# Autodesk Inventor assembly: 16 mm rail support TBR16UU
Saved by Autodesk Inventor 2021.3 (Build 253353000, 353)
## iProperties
Created: 2022-03
Part Number: 16 mm rail support TBR16UU
Document SubType Name: Assembly
Designer: Administrator
Title: 16 mm rail support TBR16UU v1
Author: Administrator
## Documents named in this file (3)
- c:\worker\convert-fusion-r02\tmp\job-1\4458\output\files\16542e95-d20b-4160-a815-438acdfd5590\2a808a41-fb52-4cbf-ad3c-1d9b1d9263a2.iam
- c:\worker\convert-fusion-r02\tmp\job-1\4458\output\files\16542e95-d20b-4160-a815-438acdfd5590\TBR16UU.ipt
- c:\worker\convert-fusion-r02\tmp\job-1\4458\output\files\16542e95-d20b-4160-a815-438acdfd5590\LM16UUOP.ipt
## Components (2 placed, 2 different names)
1. TBR16UU:1
2. LM16UUOP:1
